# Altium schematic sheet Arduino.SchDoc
size A3
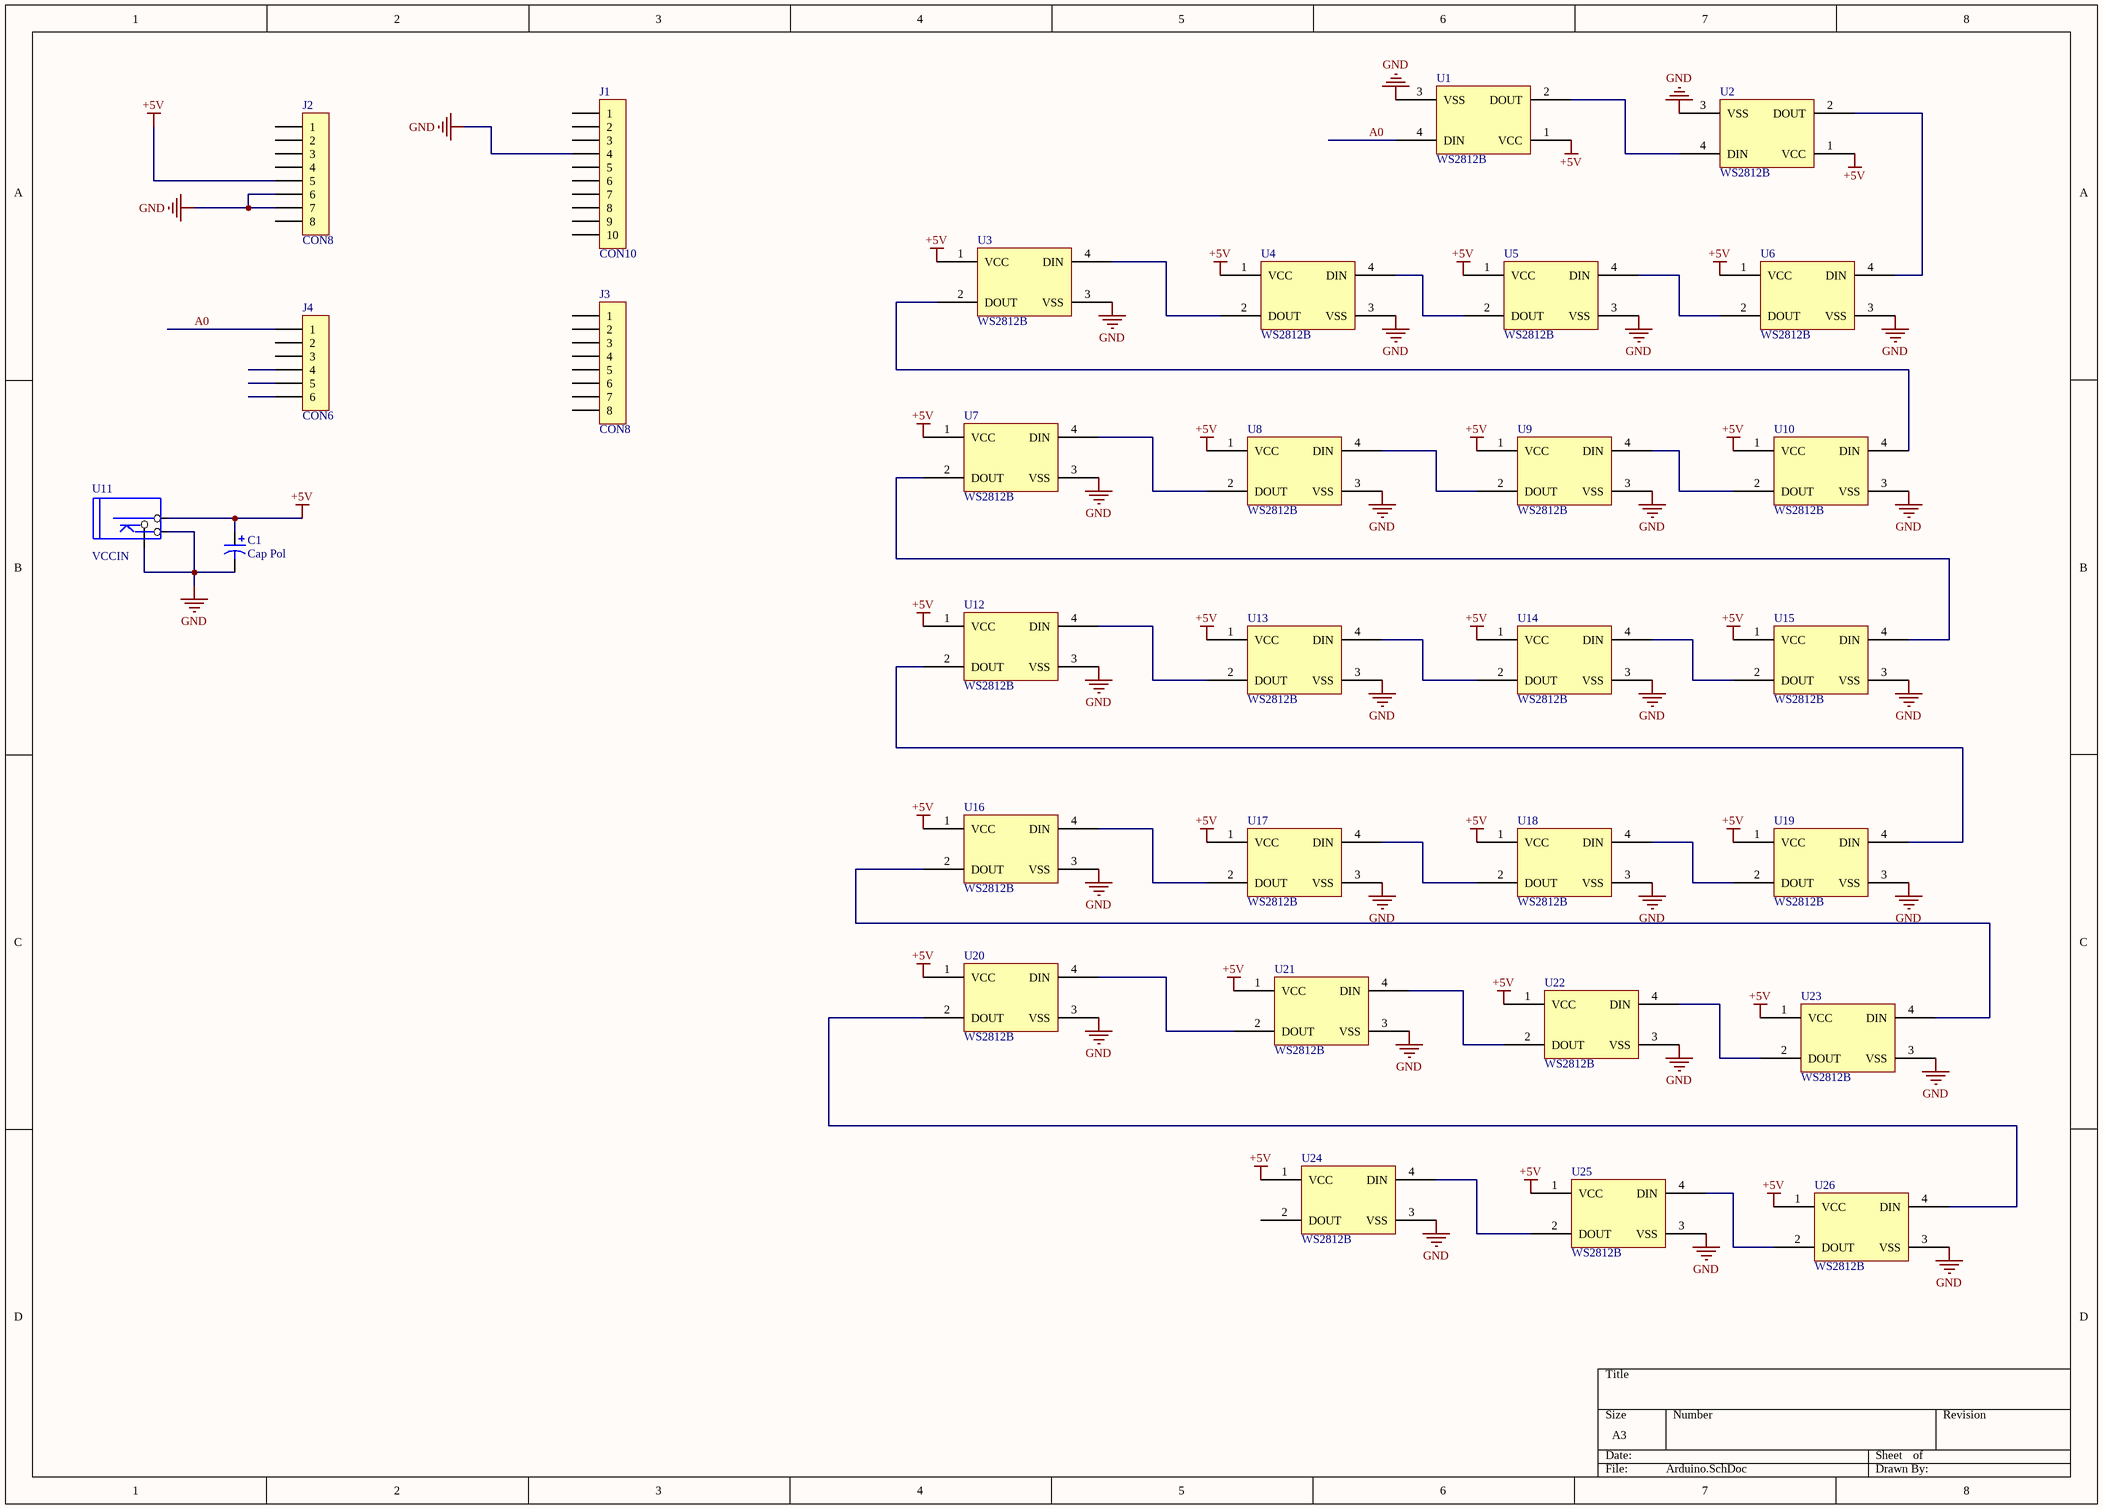
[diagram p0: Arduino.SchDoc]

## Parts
C1  Cap Pol  [CAP-TH_BD8.0-P3.50-D1.0-FD]
J1  CON10  [HDR1X10Z]
J2  CON8  [HDR1X8Z]
J3  CON8  [HDR1X8Z]
J4  CON6  [HDR1X6Z]
U1  WS2812B  [LED-SMD_4P-L5.0-W5.0-TL]
U2  WS2812B  [LED-SMD_4P-L5.0-W5.0-TL]
U3  WS2812B  [LED-SMD_4P-L5.0-W5.0-TL]
U4  WS2812B  [LED-SMD_4P-L5.0-W5.0-TL]
U5  WS2812B  [LED-SMD_4P-L5.0-W5.0-TL]
U6  WS2812B  [LED-SMD_4P-L5.0-W5.0-TL]
U7  WS2812B  [LED-SMD_4P-L5.0-W5.0-TL]
U8  WS2812B  [LED-SMD_4P-L5.0-W5.0-TL]
U9  WS2812B  [LED-SMD_4P-L5.0-W5.0-TL]
U10  WS2812B  [LED-SMD_4P-L5.0-W5.0-TL]
U11  VCCIN  [VCCIN]
U12  WS2812B  [LED-SMD_4P-L5.0-W5.0-TL]
U13  WS2812B  [LED-SMD_4P-L5.0-W5.0-TL]
U14  WS2812B  [LED-SMD_4P-L5.0-W5.0-TL]
U15  WS2812B  [LED-SMD_4P-L5.0-W5.0-TL]
U16  WS2812B  [LED-SMD_4P-L5.0-W5.0-TL]
U17  WS2812B  [LED-SMD_4P-L5.0-W5.0-TL]
U18  WS2812B  [LED-SMD_4P-L5.0-W5.0-TL]
U19  WS2812B  [LED-SMD_4P-L5.0-W5.0-TL]
U20  WS2812B  [LED-SMD_4P-L5.0-W5.0-TL]
U21  WS2812B  [LED-SMD_4P-L5.0-W5.0-TL]
U22  WS2812B  [LED-SMD_4P-L5.0-W5.0-TL]
U23  WS2812B  [LED-SMD_4P-L5.0-W5.0-TL]
U24  WS2812B  [LED-SMD_4P-L5.0-W5.0-TL]
U25  WS2812B  [LED-SMD_4P-L5.0-W5.0-TL]
U26  WS2812B  [LED-SMD_4P-L5.0-W5.0-TL]

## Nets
+5V: C1.1 J2.5 U1.1(VCC) U2.1(VCC) U3.1(VCC) U4.1(VCC) U5.1(VCC) U6.1(VCC) U7.1(VCC) U8.1(VCC) U9.1(VCC) U10.1(VCC) U11.2 U12.1(VCC) U13.1(VCC) U14.1(VCC) U15.1(VCC) U16.1(VCC) U17.1(VCC) U18.1(VCC) U19.1(VCC) U20.1(VCC) U21.1(VCC) U22.1(VCC) U23.1(VCC) U24.1(VCC) U25.1(VCC) U26.1(VCC)
GND: C1.2 J1.4 J2.6 J2.7 U1.3(VSS) U2.3(VSS) U3.3(VSS) U4.3(VSS) U5.3(VSS) U6.3(VSS) U7.3(VSS) U8.3(VSS) U9.3(VSS) U10.3(VSS) U11.1 U11.3 U12.3(VSS) U13.3(VSS) U14.3(VSS) U15.3(VSS) U16.3(VSS) U17.3(VSS) U18.3(VSS) U19.3(VSS) U20.3(VSS) U21.3(VSS) U22.3(VSS) U23.3(VSS) U24.3(VSS) U25.3(VSS) U26.3(VSS)
A0: J4.1 U1.4(DIN)
NetU1_2: U1.2(DOUT) U2.4(DIN)
NetU2_2: U2.2(DOUT) U6.4(DIN)
NetU3_2: U3.2(DOUT) U10.4(DIN)
NetU3_4: U3.4(DIN) U4.2(DOUT)
NetU4_4: U4.4(DIN) U5.2(DOUT)
NetU5_4: U5.4(DIN) U6.2(DOUT)
NetU7_2: U7.2(DOUT) U15.4(DIN)
NetU7_4: U7.4(DIN) U8.2(DOUT)
NetU8_4: U8.4(DIN) U9.2(DOUT)
NetU9_4: U9.4(DIN) U10.2(DOUT)
NetU12_2: U12.2(DOUT) U19.4(DIN)
NetU12_4: U12.4(DIN) U13.2(DOUT)
NetU13_4: U13.4(DIN) U14.2(DOUT)
NetU14_4: U14.4(DIN) U15.2(DOUT)
NetU16_2: U16.2(DOUT) U23.4(DIN)
NetU16_4: U16.4(DIN) U17.2(DOUT)
NetU17_4: U17.4(DIN) U18.2(DOUT)
NetU18_4: U18.4(DIN) U19.2(DOUT)
NetU20_2: U20.2(DOUT) U26.4(DIN)
NetU20_4: U20.4(DIN) U21.2(DOUT)
NetU21_4: U21.4(DIN) U22.2(DOUT)
NetU22_4: U22.4(DIN) U23.2(DOUT)
NetU24_4: U24.4(DIN) U25.2(DOUT)
NetU25_4: U25.4(DIN) U26.2(DOUT)

Not connected (* = marked no-connect by the designer): J1 1 2 3 5 6 7 8 9 10; J2 1 2 3 4 8; J3 1 2 3 4 5 6 7 8; J4 2 3 4 5 6; U24 2(DOUT)

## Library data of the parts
C1 = Cap Pol: Polarized Capacitor
J1 = CON10: Connector
J2 J3 = CON8: Connector
J4 = CON6: Connector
